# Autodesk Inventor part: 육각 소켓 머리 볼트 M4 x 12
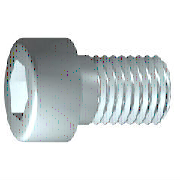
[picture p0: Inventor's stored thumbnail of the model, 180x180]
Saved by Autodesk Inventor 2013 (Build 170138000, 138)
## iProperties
IsCustomPart: 1
Created: 2012-02
Part Number: 육각 소켓 머리 볼트 M4 x 12
Material: 스테인리스강
Description: 6각 소켓 머리 캡 나사
Document SubType Name: Modeling
Standard: ISO 4762
Designer: mdu-01
Standard Revision: Fourth edition 2004-03-01
Standards Organization: ISO
Language: ko-KR
Size Designation: M4 x 12
Categories: <MemberInstance><Categories><Category DisplayName="조임쇠" InternalName="e4da775c-781d-43d5-af7c-5136215cf5a6" Mnemonic="FSTN"><Category DisplayName="볼트" InternalN
Density: 7.75 g/cm^3
Mass: 2.20337 g
Surface Area: 3.30853 cm^2
Volume: 0.284306 cm^3
Author: mdu-01
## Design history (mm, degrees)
sketch "스케치1"
  geometry: L1 (-1, 0)-(12, 0); L2 (12, 0)-(12, 2); L3 (12, 2)-(1.75, 2); L4 (1.75, 2)-(1.32, 2); L5 (1.32, 2)-(0, 2); L6 (0, 2)-(0, 3.5); L7 (0, 3.5)-(-4, 3.5); L8 (-4, 3.5)-(-4, 1.732); L9 (-4, 1.732)-(-2, 1.732); L10 (-2, 1.732)-(-1, 0); L11 (-7.2, 0)-(15.2, 0) reference; L12 (0, -0.7)-(0, 4.2) reference; L13 (1.75, 2)-(0, 2)
  constraints: 22 end point, 6 parallel, 2 collinear, 2 perpendicular, 1 horizontal, 1 point on line
  dimensions: "d1" = 10.25 distance from line of L3.end L2 (= GEL); "d2" = 0.42952 distance of L4.end L3.end (computed from GAL); "d3" = 4 distance between parallel lines of L8 L6 (= KOH); "d4" = 2 distance of L8.end L9.end (= INTI); "d5" = 60 deg angle of L10 L1; "d6" = 4 diameter of L3 L1 (= GD); "d7" = 4 diameter of L5 L1 (= BDM); "d8" = 3.4641 diameter of L9 L1 (= 1.1547 x SW); "d9" = 7 diameter of L7 L1 (= KOD); "d26" = 12 distance between parallel lines of L12 L2 (= NLG)
revolve "본체" sketch "스케치1" stored, may be unused: angle "d10" = 90 deg
sketch "스케치2"
  geometry: L1 (0, -4.9)-(0, 4.9) reference; L2 (-4.9, 0)-(4.9, 0) reference; L3 (1.732, 0)-(0.866, -1.5); L4 (0.866, -1.5)-(-0.866, -1.5); L5 (-0.866, -1.5)-(-1.732, 0); L6 (-1.732, 0)-(-0.866, 1.5); L7 (-0.866, 1.5)-(0.866, 1.5); L8 (0.866, 1.5)-(1.732, 0); 2 further points
  constraints: 12 end point, 1 coincident, 1 horizontal alignment, 1 point on line, 12 other
extrude "슬롯" join sketch "스케치2" stored distance "d11" = 10; taper "d12" = 0 deg
workplane "Work Plane1"
fillet "Fillet2" dims "d30" = 0.1 (= R)
body "Solid1"
fillet "모깎기1" dims "d17" = 0.4 (= RR)
feature "스레드" dims "d13" = 10.25 (= GEL), "d14" = 0
chamfer "모따기1" distance "d15" = 0.42941 (= -0.5 x SPD + 0.5 x GD); stored, may be unused: second distance "d16" = 0.42941 (= GUL), angle "d27" = 45 deg
other parameters: "GD" = 4 [user parameter; used in 2 equation terms], "NLG" = 12 [user parameter; used in 1 equation term], "GEL" = 10.25 [user parameter; used in 2 equation terms], "KOD" = 7 [user parameter; used in 1 equation term], "KOH" = 4 [user parameter; used in 1 equation term], "INTI" = 2 [user parameter; used in 1 equation term], "GAL" = 0.42941 (= 0.61345 x PTC) [user parameter; used in 1 equation term], "GUL" = 0.42941 (= 0.61345 x PTC) [user parameter; used in 1 equation term], "BDM" = 4 (= NND) [user parameter; used in 1 equation term], "SW" = 3 [user parameter; used in 2 equation terms], "RR" = 0.4 [user parameter; used in 1 equation term], "SPD" = 3.14117 (= NND - 1.2269 x PTC) [user parameter; used in 1 equation term], "d19" = 0, "d28" = 0, "d29" = 0, "R" = 0.1 [user parameter; used in 1 equation term], "TOA" = 30 deg [user parameter], "GD1" = 3.14117 (= THREADDIA - 1.2269 x PTC) [user parameter], "THREADDIA" = 4 [user parameter; used in 1 equation term], "FAWI" = 45 deg [user parameter], "TPU" = 14.28571 (computed from PTC) [user parameter], "PTC" = 0.7 [user parameter; used in 5 equation terms], "NND" = 4 [user parameter; used in 2 equation terms], "E0" = 3.465 (= 1.155 x SW) [user parameter]
